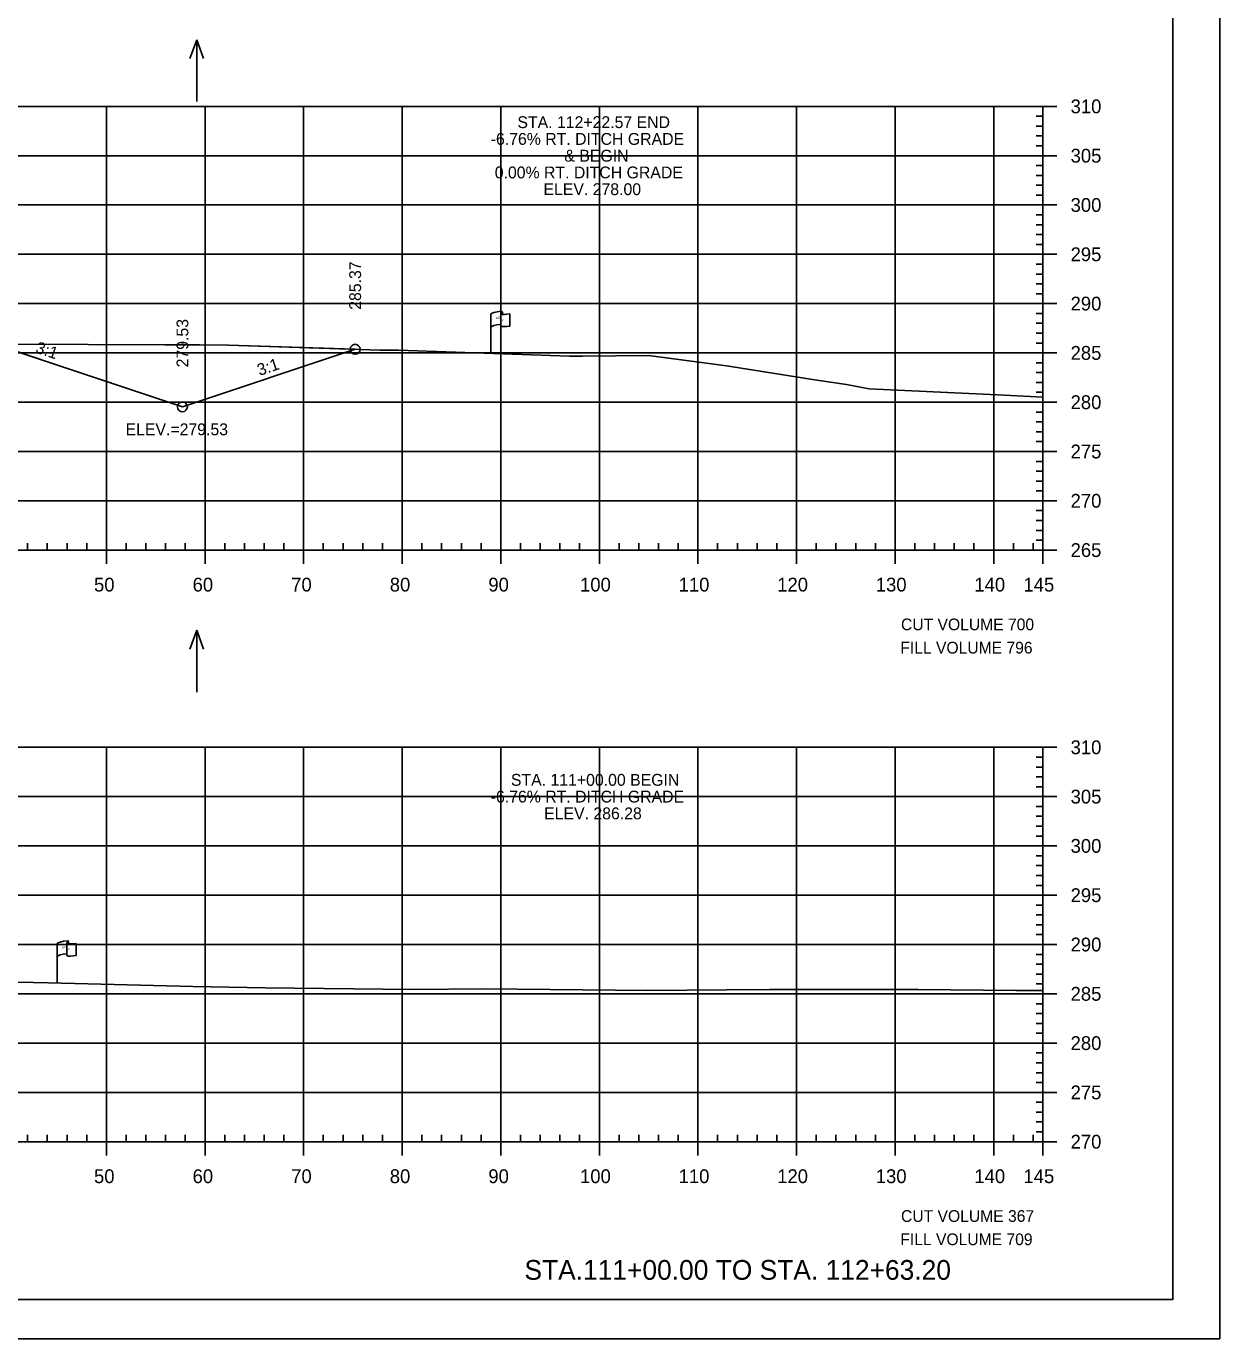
# Model space of a CAD drawing. Extents: x 1370843 to 1371177, y 380307 to 382654.
# Drawn here: x 1371055.6 to 1371176.6, y 381160.8 to 381293.9 of the extents above; entities that cross this region are included whole.
import ezdxf

# ---------------------------------------------------------------- set-up
doc = ezdxf.new("R2010")
doc.units = 0
for name, color, linetype in [('R_Axis', 7, 'Continuous'), ('R_Axis Annot', 7, 'Continuous'), ('R_Border', 7, 'Continuous'), ('R_Border Notes', 7, 'Continuous'), ('R_Draft', 7, 'Continuous'), ('R_Exist Surface', 7, 'Continuous'), ('R_Fin Surface', 7, 'Continuous'), ('R_Fin Surface Annot', 7, 'Continuous'), ('R_Grid', 7, 'Continuous'), ('R_No Plot', 7, 'Continuous'), ('R_ROW', 7, 'Continuous'), ('R_Water Annot', 7, 'Continuous')]:
    doc.layers.add(name, color=color, linetype=linetype)

msp = doc.modelspace()

# ---------------------------------------------------------------- linework, layer by layer
at = {"layer": 'R_Axis'}
for p, q in [((1371158.71, 381240.8), (1371158.71, 381285.8)), ((1371160.11, 381285.8), (1371158.71, 381285.8)), ((1371158.71, 381284.8), (1371158.01, 381284.8)), ((1371158.71, 381283.8), (1371158.01, 381283.8)), ((1371158.71, 381282.8), (1371158.01, 381282.8)), ((1371158.71, 381281.8), (1371158.01, 381281.8)), ((1371160.11, 381280.8), (1371158.71, 381280.8)), ((1371158.71, 381279.8), (1371158.01, 381279.8)), ((1371158.71, 381278.8), (1371158.01, 381278.8)), ((1371158.71, 381277.8), (1371158.01, 381277.8)), ((1371158.71, 381276.8), (1371158.01, 381276.8)), ((1371160.11, 381275.8), (1371158.71, 381275.8)), ((1371158.71, 381274.8), (1371158.01, 381274.8)), ((1371158.71, 381273.8), (1371158.01, 381273.8)), ((1371158.71, 381272.8), (1371158.01, 381272.8)), ((1371158.71, 381271.8), (1371158.01, 381271.8)), ((1371158.71, 381269.8), (1371158.01, 381269.8)), ((1371160.11, 381270.8), (1371158.71, 381270.8)), ((1371158.71, 381268.8), (1371158.01, 381268.8)), ((1371158.71, 381267.8), (1371158.01, 381267.8)), ((1371158.71, 381266.8), (1371158.01, 381266.8)), ((1371160.11, 381265.8), (1371158.71, 381265.8)), ((1371158.71, 381264.8), (1371158.01, 381264.8)), ((1371158.71, 381263.8), (1371158.01, 381263.8)), ((1371158.71, 381262.8), (1371158.01, 381262.8)), ((1371158.71, 381261.8), (1371158.01, 381261.8)), ((1371160.11, 381260.8), (1371158.71, 381260.8)), ((1371158.71, 381259.8), (1371158.01, 381259.8)), ((1371158.71, 381258.8), (1371158.01, 381258.8)), ((1371158.71, 381257.8), (1371158.01, 381257.8)), ((1371158.71, 381256.8), (1371158.01, 381256.8)), ((1371160.11, 381255.8), (1371158.71, 381255.8)), ((1371158.71, 381254.8), (1371158.01, 381254.8)), ((1371158.71, 381253.8), (1371158.01, 381253.8)), ((1371158.71, 381252.8), (1371158.01, 381252.8)), ((1371158.71, 381251.8), (1371158.01, 381251.8)), ((1371158.71, 381249.8), (1371158.01, 381249.8)), ((1371160.11, 381250.8), (1371158.71, 381250.8)), ((1371158.71, 381248.8), (1371158.01, 381248.8)), ((1371158.71, 381247.8), (1371158.01, 381247.8)), ((1371158.71, 381246.8), (1371158.01, 381246.8)), ((1371160.11, 381245.8), (1371158.71, 381245.8)), ((1371158.71, 381244.8), (1371158.01, 381244.8)), ((1371158.71, 381243.8), (1371158.01, 381243.8)), ((1371158.71, 381242.8), (1371158.01, 381242.8)), ((1371158.71, 381241.8), (1371158.01, 381241.8)), ((1370868.71, 381240.8), (1371158.71, 381240.8)), ((1371055.71, 381240.8), (1371055.71, 381241.5)), ((1371057.71, 381240.8), (1371057.71, 381241.5)), ((1371059.71, 381240.8), (1371059.71, 381241.5)), ((1371061.71, 381240.8), (1371061.71, 381241.5)), ((1371063.71, 381239.4), (1371063.71, 381240.8)), ((1371065.71, 381240.8), (1371065.71, 381241.5)), ((1371067.71, 381240.8), (1371067.71, 381241.5)), ((1371069.71, 381240.8), (1371069.71, 381241.5)), ((1371071.71, 381240.8), (1371071.71, 381241.5)), ((1371073.71, 381239.4), (1371073.71, 381240.8)), ((1371075.71, 381240.8), (1371075.71, 381241.5)), ((1371077.71, 381240.8), (1371077.71, 381241.5)), ((1371079.71, 381240.8), (1371079.71, 381241.5)), ((1371081.71, 381240.8), (1371081.71, 381241.5)), ((1371083.71, 381239.4), (1371083.71, 381240.8)), ((1371085.71, 381240.8), (1371085.71, 381241.5)), ((1371087.71, 381240.8), (1371087.71, 381241.5)), ((1371089.71, 381240.8), (1371089.71, 381241.5)), ((1371091.71, 381240.8), (1371091.71, 381241.5)), ((1371093.71, 381239.4), (1371093.71, 381240.8)), ((1371095.71, 381240.8), (1371095.71, 381241.5)), ((1371097.71, 381240.8), (1371097.71, 381241.5)), ((1371099.71, 381240.8), (1371099.71, 381241.5)), ((1371101.71, 381240.8), (1371101.71, 381241.5)), ((1371103.71, 381239.4), (1371103.71, 381240.8)), ((1371105.71, 381240.8), (1371105.71, 381241.5)), ((1371107.71, 381240.8), (1371107.71, 381241.5)), ((1371109.71, 381240.8), (1371109.71, 381241.5)), ((1371111.71, 381240.8), (1371111.71, 381241.5)), ((1371113.71, 381239.4), (1371113.71, 381240.8)), ((1371115.71, 381240.8), (1371115.71, 381241.5)), ((1371117.71, 381240.8), (1371117.71, 381241.5)), ((1371119.71, 381240.8), (1371119.71, 381241.5)), ((1371121.71, 381240.8), (1371121.71, 381241.5)), ((1371123.71, 381239.4), (1371123.71, 381240.8)), ((1371125.71, 381240.8), (1371125.71, 381241.5)), ((1371127.71, 381240.8), (1371127.71, 381241.5)), ((1371129.71, 381240.8), (1371129.71, 381241.5)), ((1371131.71, 381240.8), (1371131.71, 381241.5)), ((1371133.71, 381239.4), (1371133.71, 381240.8)), ((1371135.71, 381240.8), (1371135.71, 381241.5)), ((1371137.71, 381240.8), (1371137.71, 381241.5)), ((1371139.71, 381240.8), (1371139.71, 381241.5)), ((1371141.71, 381240.8), (1371141.71, 381241.5)), ((1371143.71, 381239.4), (1371143.71, 381240.8)), ((1371145.71, 381240.8), (1371145.71, 381241.5)), ((1371147.71, 381240.8), (1371147.71, 381241.5)), ((1371149.71, 381240.8), (1371149.71, 381241.5)), ((1371151.71, 381240.8), (1371151.71, 381241.5)), ((1371153.71, 381239.4), (1371153.71, 381240.8)), ((1371155.71, 381240.8), (1371155.71, 381241.5)), ((1371157.71, 381240.8), (1371157.71, 381241.5)), ((1371158.71, 381239.4), (1371158.71, 381240.8)), ((1371160.11, 381240.8), (1371158.71, 381240.8)), ((1371158.71, 381180.8), (1371158.71, 381220.8)), ((1371160.11, 381220.8), (1371158.71, 381220.8)), ((1371158.71, 381219.8), (1371158.01, 381219.8)), ((1371158.71, 381218.8), (1371158.01, 381218.8)), ((1371158.71, 381217.8), (1371158.01, 381217.8)), ((1371158.71, 381216.8), (1371158.01, 381216.8)), ((1371160.11, 381215.8), (1371158.71, 381215.8)), ((1371158.71, 381214.8), (1371158.01, 381214.8)), ((1371158.71, 381213.8), (1371158.01, 381213.8)), ((1371158.71, 381212.8), (1371158.01, 381212.8)), ((1371158.71, 381211.8), (1371158.01, 381211.8)), ((1371158.71, 381209.8), (1371158.01, 381209.8)), ((1371160.11, 381210.8), (1371158.71, 381210.8)), ((1371158.71, 381208.8), (1371158.01, 381208.8)), ((1371158.71, 381207.8), (1371158.01, 381207.8)), ((1371158.71, 381206.8), (1371158.01, 381206.8)), ((1371160.11, 381205.8), (1371158.71, 381205.8)), ((1371158.71, 381204.8), (1371158.01, 381204.8)), ((1371158.71, 381203.8), (1371158.01, 381203.8)), ((1371158.71, 381202.8), (1371158.01, 381202.8)), ((1371158.71, 381201.8), (1371158.01, 381201.8)), ((1371160.11, 381200.8), (1371158.71, 381200.8)), ((1371158.71, 381199.8), (1371158.01, 381199.8)), ((1371158.71, 381198.8), (1371158.01, 381198.8)), ((1371158.71, 381197.8), (1371158.01, 381197.8)), ((1371158.71, 381196.8), (1371158.01, 381196.8)), ((1371160.11, 381195.8), (1371158.71, 381195.8)), ((1371158.71, 381194.8), (1371158.01, 381194.8)), ((1371158.71, 381193.8), (1371158.01, 381193.8)), ((1371158.71, 381192.8), (1371158.01, 381192.8)), ((1371158.71, 381191.8), (1371158.01, 381191.8)), ((1371160.11, 381190.8), (1371158.71, 381190.8)), ((1371158.71, 381189.8), (1371158.01, 381189.8)), ((1371158.71, 381188.8), (1371158.01, 381188.8)), ((1371158.71, 381187.8), (1371158.01, 381187.8)), ((1371158.71, 381186.8), (1371158.01, 381186.8)), ((1371158.71, 381184.8), (1371158.01, 381184.8)), ((1371160.11, 381185.8), (1371158.71, 381185.8)), ((1371158.71, 381183.8), (1371158.01, 381183.8)), ((1371158.71, 381182.8), (1371158.01, 381182.8)), ((1370868.71, 381180.8), (1371158.71, 381180.8)), ((1371055.71, 381180.8), (1371055.71, 381181.5)), ((1371057.71, 381180.8), (1371057.71, 381181.5)), ((1371059.71, 381180.8), (1371059.71, 381181.5)), ((1371061.71, 381180.8), (1371061.71, 381181.5)), ((1371063.71, 381179.4), (1371063.71, 381180.8)), ((1371065.71, 381180.8), (1371065.71, 381181.5)), ((1371067.71, 381180.8), (1371067.71, 381181.5)), ((1371069.71, 381180.8), (1371069.71, 381181.5)), ((1371071.71, 381180.8), (1371071.71, 381181.5)), ((1371073.71, 381179.4), (1371073.71, 381180.8)), ((1371075.71, 381180.8), (1371075.71, 381181.5)), ((1371077.71, 381180.8), (1371077.71, 381181.5)), ((1371079.71, 381180.8), (1371079.71, 381181.5)), ((1371081.71, 381180.8), (1371081.71, 381181.5)), ((1371083.71, 381179.4), (1371083.71, 381180.8)), ((1371085.71, 381180.8), (1371085.71, 381181.5)), ((1371087.71, 381180.8), (1371087.71, 381181.5)), ((1371089.71, 381180.8), (1371089.71, 381181.5)), ((1371091.71, 381180.8), (1371091.71, 381181.5)), ((1371093.71, 381179.4), (1371093.71, 381180.8)), ((1371095.71, 381180.8), (1371095.71, 381181.5)), ((1371097.71, 381180.8), (1371097.71, 381181.5)), ((1371099.71, 381180.8), (1371099.71, 381181.5)), ((1371101.71, 381180.8), (1371101.71, 381181.5)), ((1371103.71, 381179.4), (1371103.71, 381180.8)), ((1371105.71, 381180.8), (1371105.71, 381181.5)), ((1371107.71, 381180.8), (1371107.71, 381181.5)), ((1371109.71, 381180.8), (1371109.71, 381181.5)), ((1371111.71, 381180.8), (1371111.71, 381181.5)), ((1371113.71, 381179.4), (1371113.71, 381180.8)), ((1371115.71, 381180.8), (1371115.71, 381181.5)), ((1371117.71, 381180.8), (1371117.71, 381181.5)), ((1371119.71, 381180.8), (1371119.71, 381181.5)), ((1371121.71, 381180.8), (1371121.71, 381181.5)), ((1371123.71, 381179.4), (1371123.71, 381180.8)), ((1371125.71, 381180.8), (1371125.71, 381181.5)), ((1371127.71, 381180.8), (1371127.71, 381181.5)), ((1371129.71, 381180.8), (1371129.71, 381181.5)), ((1371131.71, 381180.8), (1371131.71, 381181.5)), ((1371133.71, 381179.4), (1371133.71, 381180.8)), ((1371135.71, 381180.8), (1371135.71, 381181.5)), ((1371137.71, 381180.8), (1371137.71, 381181.5)), ((1371139.71, 381180.8), (1371139.71, 381181.5)), ((1371141.71, 381180.8), (1371141.71, 381181.5)), ((1371143.71, 381179.4), (1371143.71, 381180.8)), ((1371145.71, 381180.8), (1371145.71, 381181.5)), ((1371147.71, 381180.8), (1371147.71, 381181.5)), ((1371149.71, 381180.8), (1371149.71, 381181.5)), ((1371151.71, 381180.8), (1371151.71, 381181.5)), ((1371153.71, 381179.4), (1371153.71, 381180.8)), ((1371155.71, 381180.8), (1371155.71, 381181.5)), ((1371157.71, 381180.8), (1371157.71, 381181.5)), ((1371158.71, 381181.8), (1371158.01, 381181.8)), ((1371158.71, 381179.4), (1371158.71, 381180.8)), ((1371160.11, 381180.8), (1371158.71, 381180.8))]:
    msp.add_line(p, q, dxfattribs=at)
at = {"layer": 'R_Border'}
for q in [(1371171.89, 381370.26), (1370855.71, 381164.8)]:
    msp.add_line((1371171.89, 381164.8), q, dxfattribs=at)
at = {"layer": 'R_Exist Surface'}
for points in [[(1371054.1, 381261.68), (1371069.64, 381261.62), (1371073.16, 381261.61), (1371076.1, 381261.6), (1371091.44, 381261.08), (1371093.35, 381261.07), (1371110.67, 381260.46), (1371111.99, 381260.47), (1371118.7, 381260.53), (1371126.62, 381259.5), (1371135.77, 381258.02), (1371138.77, 381257.58), (1371141.09, 381257.16), (1371154.82, 381256.5), (1371158.71, 381256.3)], [(1371039.3, 381197.33), (1371057.83, 381196.93), (1371072.48, 381196.53), (1371079.81, 381196.41), (1371094.73, 381196.25), (1371102.14, 381196.32), (1371118.58, 381196.13), (1371126.62, 381196.19), (1371130.99, 381196.23), (1371146.01, 381196.24), (1371155.97, 381196.14), (1371158.71, 381196.14)]]:
    msp.add_lwpolyline(points, dxfattribs=at)
at = {"layer": 'R_Fin Surface'}
msp.add_lwpolyline([(1370929.49, 381265.86), (1370983.71, 381266.95), (1370993.71, 381267.15), (1370996.17, 381267.76), (1371000.71, 381268.9), (1371002.71, 381268.98), (1371013.71, 381269.2), (1371024.71, 381268.98), (1371026.71, 381268.9), (1371031.25, 381267.76), (1371042.71, 381264.9), (1371071.42, 381255.33), (1371088.94, 381261.17)], dxfattribs=at)
at = {"layer": 'R_Grid'}
for p, q in [((1370868.71, 381285.8), (1371158.71, 381285.8)), ((1371063.71, 381240.8), (1371063.71, 381285.8)), ((1371073.71, 381240.8), (1371073.71, 381285.8)), ((1371083.71, 381240.8), (1371083.71, 381285.8)), ((1371093.71, 381240.8), (1371093.71, 381285.8)), ((1371103.71, 381240.8), (1371103.71, 381285.8)), ((1371113.71, 381240.8), (1371113.71, 381285.8)), ((1371123.71, 381240.8), (1371123.71, 381285.8)), ((1371133.71, 381240.8), (1371133.71, 381285.8)), ((1371143.71, 381240.8), (1371143.71, 381285.8)), ((1371153.71, 381240.8), (1371153.71, 381285.8)), ((1371158.71, 381240.8), (1371158.71, 381285.8)), ((1370868.71, 381280.8), (1371158.71, 381280.8)), ((1370868.71, 381275.8), (1371158.71, 381275.8)), ((1370868.71, 381270.8), (1371158.71, 381270.8)), ((1370868.71, 381265.8), (1371158.71, 381265.8)), ((1370868.71, 381260.8), (1371158.71, 381260.8)), ((1370868.71, 381255.8), (1371158.71, 381255.8)), ((1370868.71, 381250.8), (1371158.71, 381250.8)), ((1370868.71, 381245.8), (1371158.71, 381245.8)), ((1370868.71, 381240.8), (1371158.71, 381240.8)), ((1370868.71, 381220.8), (1371158.71, 381220.8)), ((1371063.71, 381180.8), (1371063.71, 381220.8)), ((1371073.71, 381180.8), (1371073.71, 381220.8)), ((1371083.71, 381180.8), (1371083.71, 381220.8)), ((1371093.71, 381180.8), (1371093.71, 381220.8)), ((1371103.71, 381180.8), (1371103.71, 381220.8)), ((1371113.71, 381180.8), (1371113.71, 381220.8)), ((1371123.71, 381180.8), (1371123.71, 381220.8)), ((1371133.71, 381180.8), (1371133.71, 381220.8)), ((1371143.71, 381180.8), (1371143.71, 381220.8)), ((1371153.71, 381180.8), (1371153.71, 381220.8)), ((1371158.71, 381180.8), (1371158.71, 381220.8)), ((1370868.71, 381215.8), (1371158.71, 381215.8)), ((1370868.71, 381210.8), (1371158.71, 381210.8)), ((1370868.71, 381205.8), (1371158.71, 381205.8)), ((1370868.71, 381200.8), (1371158.71, 381200.8)), ((1370868.71, 381195.8), (1371158.71, 381195.8)), ((1370868.71, 381190.8), (1371158.71, 381190.8)), ((1370868.71, 381185.8), (1371158.71, 381185.8)), ((1370868.71, 381180.8), (1371158.71, 381180.8))]:
    msp.add_line(p, q, dxfattribs=at)
at = {"layer": 'R_No Plot'}
msp.add_line((1370843.31, 381160.82), (1371176.64, 381160.82), dxfattribs=at)
for points in [[(1370843.3, 381374.15), (1371176.64, 381374.15), (1371176.64, 381160.82), (1370843.3, 381160.82)], [(1371089.63, 381370.26), (1371089.63, 381360.38), (1371125.36, 381360.38), (1371125.36, 381357.46), (1371148.56, 381357.46), (1371148.56, 381333.13), (1371171.89, 381333.13), (1371171.89, 381164.8), (1370855.71, 381164.8), (1370855.71, 381370.26)], [(1371052.33, 381261.69), (1371071.42, 381255.33), (1371088.94, 381261.17), (1371076.1, 381261.6), (1371073.16, 381261.61), (1371069.64, 381261.62), (1371054.1, 381261.68)]]:
    msp.add_lwpolyline(points, close=True, dxfattribs=at)
for centre in [(1371088.94, 381261.17), (1371071.42, 381255.33)]:
    msp.add_circle(centre, 0.5, dxfattribs=at)
at = {"layer": 'R_ROW'}
for p, q in [((1371102.71, 381260.74), (1371102.71, 381264.69)), ((1371103.7, 381264.78), (1371103.7, 381264.77)), ((1371103.7, 381264.77), (1371103.7, 381263.54)), ((1371103.87, 381264.94), (1371103.87, 381264.7)), ((1371104.64, 381264.75), (1371104.64, 381263.51)), ((1371058.71, 381196.9), (1371058.71, 381200.85)), ((1371059.7, 381200.95), (1371059.7, 381200.93)), ((1371059.7, 381200.93), (1371059.7, 381199.71)), ((1371059.87, 381201.1), (1371059.87, 381200.86)), ((1371060.64, 381200.91), (1371060.64, 381199.67))]:
    msp.add_line(p, q, dxfattribs=at)
for centre, radius, start, end in [((1371103.78, 381264.78), 0.078, 88.6458, 274.2828), ((1371103.79, 381264.94), 0.0783, 263.0712, 93.9564), ((1371103.78, 381263.54), 0.0783, 180, 273.9564), ((1371059.78, 381200.95), 0.078, 88.6458, 274.2828), ((1371059.79, 381201.1), 0.0783, 263.0712, 93.9564), ((1371059.78, 381199.71), 0.0783, 180, 273.9564)]:
    msp.add_arc(centre, radius, start, end, dxfattribs=at)
for centre, major_axis, ratio, start_param, end_param in [((1371104.29, 381264.73), (-1.58, -0.04), 0.19887, 5.030368, 6.283185), ((1371105, 381264.85), (-1.23, -0.13), 0.052933, 0.159456, 1.268315), ((1371104.29, 381263.41), (-1.58, -0.04), 0.19887, 5.083035, 6.194897), ((1371105, 381263.61), (-1.23, -0.13), 0.052933, 0.159456, 1.268315), ((1371060.29, 381200.9), (-1.58, -0.04), 0.19887, 5.030368, 6.283185), ((1371061, 381201.01), (-1.23, -0.13), 0.052933, 0.159456, 1.268315), ((1371060.29, 381199.58), (-1.58, -0.04), 0.19887, 5.083035, 6.194897), ((1371061, 381199.77), (-1.23, -0.13), 0.052933, 0.159456, 1.268315)]:
    msp.add_ellipse(centre, major_axis=major_axis, ratio=ratio, start_param=start_param, end_param=end_param, dxfattribs=at)
at = {"layer": 'R_Water Annot'}
for p, q in [((1371072.87, 381292.56), (1371072.17, 381290.64)), ((1371072.87, 381286.28), (1371072.87, 381292.56)), ((1371072.87, 381292.56), (1371073.57, 381290.64)), ((1371072.87, 381232.67), (1371072.17, 381230.75)), ((1371072.87, 381226.39), (1371072.87, 381232.67)), ((1371072.87, 381232.67), (1371073.57, 381230.75))]:
    msp.add_line(p, q, dxfattribs=at)

# ---------------------------------------------------------------- texts
at = {"layer": 'R_Axis Annot'}
for s, p in [('310', (1371161.51, 381285.1)), ('305', (1371161.51, 381280.1)), ('300', (1371161.51, 381275.1)), ('295', (1371161.51, 381270.1)), ('290', (1371161.51, 381265.1)), ('285', (1371161.51, 381260.1)), ('280', (1371161.51, 381255.1)), ('275', (1371161.51, 381250.1)), ('270', (1371161.51, 381245.1)), ('265', (1371161.51, 381240.1)), ('50', (1371062.45, 381236.6)), ('60', (1371072.45, 381236.6)), ('70', (1371082.45, 381236.6)), ('80', (1371092.45, 381236.6)), ('90', (1371102.45, 381236.6)), ('100', (1371111.75, 381236.6)), ('110', (1371121.75, 381236.6)), ('120', (1371131.75, 381236.6)), ('130', (1371141.75, 381236.6)), ('140', (1371151.75, 381236.6)), ('145', (1371156.73, 381236.6)), ('310', (1371161.51, 381220.1)), ('305', (1371161.51, 381215.1)), ('300', (1371161.51, 381210.1)), ('295', (1371161.51, 381205.1)), ('290', (1371161.51, 381200.1)), ('285', (1371161.51, 381195.1)), ('280', (1371161.51, 381190.1)), ('275', (1371161.51, 381185.1)), ('270', (1371161.51, 381180.1)), ('50', (1371062.45, 381176.6)), ('60', (1371072.45, 381176.6)), ('70', (1371082.45, 381176.6)), ('80', (1371092.45, 381176.6)), ('90', (1371102.45, 381176.6)), ('100', (1371111.75, 381176.6)), ('110', (1371121.75, 381176.6)), ('120', (1371131.75, 381176.6)), ('130', (1371141.75, 381176.6)), ('140', (1371151.75, 381176.6)), ('145', (1371156.73, 381176.6))]:
    msp.add_text(s, height=1.4, dxfattribs=at).set_placement(p)
at = {"layer": 'R_Border Notes'}
for s, p in [('CUT VOLUME 700', (1371144.31, 381232.67)), ('FILL VOLUME 796', (1371144.24, 381230.31)), ('CUT VOLUME 367', (1371144.31, 381172.67)), ('FILL VOLUME 709', (1371144.24, 381170.31))]:
    msp.add_text(s, height=1.1875, dxfattribs=at).set_placement(p)
at = {"layer": 'R_Draft'}
msp.add_text('STA.111+00.00 TO STA. 112+63.20', height=2, dxfattribs=at).set_placement((1371106.11, 381166.8))
at = {"layer": 'R_Fin Surface Annot'}
for s, rotation, p in [('285.37', 90, (1371089.54, 381265.17)), ('279.53', 90, (1371072.02, 381259.33)), ('3:1', 341.5651, (1371056.44, 381260.85)), ('3:1', 18.4349, (1371079.23, 381258.46))]:
    msp.add_text(s, height=1.2, rotation=rotation, dxfattribs=at).set_placement(p)
at = {"layer": 'R_ROW'}
for s, height, rotation, p in [('R ', 0.2, 9.9884, (1371103.23, 381264.19)), (' O', 0.2, 9.9884, (1371103.37, 381264.24)), ('DWB 11-9-07', 0.001, 90, (1371103.87, 381264.7)), ('W', 0.2, 351.1788, (1371103.7, 381264.07)), ('DWB 11-9-07', 0.001, 5.0717, (1371104.63, 381263.51)), ('DWB 11-9-07', 0.001, 90, (1371102.71, 381260.74)), ('R ', 0.2, 9.9884, (1371059.23, 381200.36)), (' O', 0.2, 9.9884, (1371059.37, 381200.4)), ('DWB 11-9-07', 0.001, 90, (1371059.87, 381200.86)), ('W', 0.2, 351.1788, (1371059.7, 381200.23)), ('DWB 11-9-07', 0.001, 5.0717, (1371060.63, 381199.67)), ('DWB 11-9-07', 0.001, 90, (1371058.71, 381196.9))]:
    msp.add_text(s, height=height, rotation=rotation, dxfattribs=at).set_placement(p)
at = {"layer": 'R_Water Annot'}
for s, p in [('STA. 112+22.57 END', (1371105.4, 381283.6)), ('-6.76% RT. DITCH GRADE', (1371102.69, 381281.9)), ('& BEGIN', (1371110.16, 381280.2)), ('0.00% RT. DITCH GRADE', (1371103.1, 381278.5)), ('ELEV. 278.00', (1371108.04, 381276.8)), ('ELEV.=279.53', (1371065.65, 381252.45)), ('STA. 111+00.00 BEGIN', (1371104.74, 381216.9)), ('-6.76% RT. DITCH GRADE', (1371102.69, 381215.2)), ('ELEV. 286.28', (1371108.11, 381213.5))]:
    msp.add_text(s, height=1.2, dxfattribs=at).set_placement(p)

doc.saveas('drawing.dxf')
